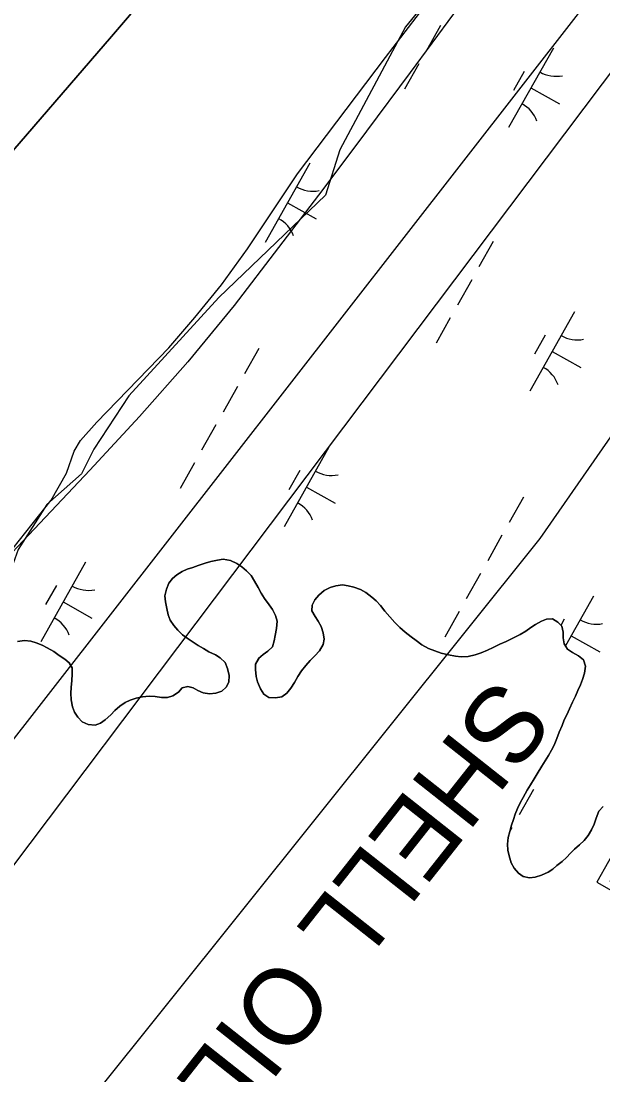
# Model space of a CAD drawing. Extents: x 3913936 to 3933962, y 195330 to 217741.
# Drawn here: x 3923117 to 3923436, y 199912 to 200489 of the extents above; entities that cross this region are included whole.
import ezdxf

# ---------------------------------------------------------------- set-up
doc = ezdxf.new("R2010")
doc.units = 0
for name, color, linetype in [('V-CHAN-DOCK', 7, 'Continuous'), ('V-RIVR-EDGE', 7, 'Continuous'), ('V-RRAP-FSHR', 7, 'Continuous'), ('V-TOPO-DPTH', 7, 'Continuous'), ('V-TOPO-MINR', 7, 'Continuous'), ('V-TOPO-SHOR', 7, 'Continuous'), ('V-UTIL-IDEN', 7, 'Continuous'), ('V-UTIL-LINE', 7, 'Continuous'), ('V-WETL-SWMP', 7, 'Continuous')]:
    doc.layers.add(name, color=color, linetype=linetype)

msp = doc.modelspace()

# ---------------------------------------------------------------- linework, layer by layer
at = {"layer": 'V-CHAN-DOCK'}
msp.add_lwpolyline([(3923458.56, 200062.78), (3923432.96, 200017.59), (3923444.96, 200010.79), (3923446.47, 200013.46), (3923481.36, 199993.7), (3923483.16, 199996.89), (3923495.74, 199989.76), (3923498.67, 199994.95), (3923485.34, 200002.5), (3923482.61, 199997.68), (3923446.17, 200018.32), (3923444.63, 200015.6), (3923440.35, 200018.02), (3923463.97, 200059.72)], close=True, dxfattribs=at)
at = {"layer": 'V-RIVR-EDGE'}
msp.add_lwpolyline([(3923413.52, 200590.76), (3923328.14, 200486.28), (3923292.19, 200418.88), (3923284.33, 200394.16), (3923225.91, 200337.99), (3923176.48, 200284.07), (3923157.38, 200254.86), (3923150.64, 200241.38), (3923131.55, 200224.53), (3923115.82, 200199.81), (3923105.71, 200171.73), (3923101.21, 200151.51), (3923091.1, 200144.77), (3923078.75, 200144.77), (3923064.14, 200130.16), (3923051.78, 200097.58), (3923032.69, 200079.61), (3923010.22, 200067.25), (3922975.39, 200050.4), (3922915.85, 200002.09), (3922760.82, 199830.21)], dxfattribs=at)
at = {"layer": 'V-RRAP-FSHR'}
msp.add_lwpolyline([(3923354.41, 200493.48), (3923330.62, 200461.33), (3923306.83, 200429.17), (3923282.85, 200397.16), (3923258.52, 200365.42), (3923234.18, 200333.67), (3923208.83, 200302.73), (3923182.44, 200272.68), (3923155.23, 200243.36), (3923127.68, 200214.36), (3923100.29, 200185.46), (3923072.29, 200156.64), (3923044.53, 200127.85), (3923016.74, 200099.77), (3922988.95, 200070.3)], dxfattribs=at)
at = {"layer": 'V-TOPO-DPTH'}
msp.add_lwpolyline([(3923572.36, 200998.52), (3923503.91, 200907.2), (3923435.27, 200816.03), (3923326.2, 200671.67), (3923311.77, 200652.93), (3923297.12, 200634.37), (3923282.13, 200616.08), (3923266.93, 200597.97), (3923166.97, 200481.11), (3923101.22, 200405.05), (3923034.94, 200329.46), (3922967.87, 200254.57), (3922900.28, 200180.15), (3922705.27, 199967.65), (3922675.93, 199934.9), (3922647.14, 199901.69), (3922619.17, 199867.8), (3922591.73, 199833.44), (3922552.62, 199783.23), (3922506.1, 199723.37), (3922459.66, 199663.45), (3922413.34, 199603.44), (3922367.1, 199543.37), (3922084.4, 199175.27)], dxfattribs=at)
at = {"layer": 'V-TOPO-MINR'}
msp.add_lwpolyline([(3922084.4, 199175.27), (3922367.1, 199543.37), (3922413.34, 199603.44), (3922459.66, 199663.45), (3922506.1, 199723.37), (3922552.62, 199783.23), (3922591.73, 199833.44), (3922619.17, 199867.8), (3922647.14, 199901.69), (3922675.93, 199934.9), (3922705.27, 199967.65), (3922900.28, 200180.15), (3922967.87, 200254.57), (3923034.94, 200329.46), (3923101.22, 200405.05), (3923166.97, 200481.11), (3923266.93, 200597.97), (3923282.13, 200616.08), (3923297.12, 200634.37), (3923311.77, 200652.93), (3923326.2, 200671.67), (3923435.27, 200816.03), (3923503.91, 200907.2), (3923572.36, 200998.52)], dxfattribs=at)
at = {"layer": 'V-TOPO-SHOR'}
for points in [[(3923168.92, 200111.58), (3923171.51, 200113.92), (3923174.44, 200116.09), (3923177.21, 200117.31), (3923180.58, 200118.45), (3923183.95, 200119.06), (3923187.67, 200119.51), (3923190.87, 200119.26), (3923194.51, 200118.75), (3923197.62, 200118.84), (3923200.56, 200119.71), (3923203.76, 200121.71), (3923205.83, 200123.97), (3923208.77, 200124.75), (3923211.71, 200124.07), (3923214.4, 200122.61), (3923217.34, 200121.4), (3923220.72, 200120.72), (3923224.26, 200121.08), (3923227.46, 200122.21), (3923229.79, 200124.47), (3923231.34, 200127.24), (3923231.5, 200130.87), (3923230.63, 200134.68), (3923229.32, 200137.96), (3923226.63, 200140.46), (3923223.95, 200142.1), (3923220.31, 200143.82), (3923217.36, 200145.54), (3923214.59, 200147.18), (3923211.73, 200149.16), (3923208.43, 200151.32), (3923206.01, 200153.13), (3923203.4, 200155.71), (3923201.15, 200158.3), (3923199.24, 200161.07), (3923198.1, 200164.09), (3923197.31, 200167.46), (3923196.61, 200171.1), (3923196.26, 200174.56), (3923197.11, 200178.19), (3923198.49, 200181.4), (3923200.47, 200183.91), (3923202.89, 200185.91), (3923205.74, 200187.82), (3923208.5, 200189.04), (3923211.53, 200190.09), (3923214.55, 200191.13), (3923218.36, 200192.44), (3923221.38, 200193.31), (3923225.19, 200194.1), (3923228.3, 200194.54), (3923232.28, 200193.86), (3923235.75, 200192.23), (3923238.52, 200190.42), (3923241.04, 200188.09), (3923243.55, 200185.59), (3923245.38, 200182.57), (3923247.38, 200179.11), (3923249.03, 200176), (3923250.86, 200173.07), (3923253.37, 200169.61), (3923255.28, 200167.02), (3923256.85, 200163.74), (3923257.81, 200160.54), (3923257.48, 200156.64), (3923256.79, 200152.75), (3923256.2, 200149.72), (3923255.17, 200146.6), (3923252.67, 200144.09), (3923250.16, 200142.35), (3923247.49, 200140.09), (3923246.02, 200137.23), (3923245.94, 200134.03), (3923246.39, 200130.31), (3923247.09, 200127.29), (3923248.74, 200123.48), (3923250.57, 200120.63), (3923253.26, 200118.82), (3923256.98, 200118.57), (3923260.35, 200119.19), (3923263.03, 200121.1), (3923265.27, 200123.79), (3923267.25, 200126.99), (3923269.06, 200130.2), (3923271.12, 200133.41), (3923273.45, 200136.36), (3923275.87, 200139.05), (3923278.37, 200141.56), (3923281.04, 200144.34), (3923283.11, 200147.72), (3923283.54, 200150.75), (3923283, 200154.12), (3923281.87, 200157.66), (3923280.31, 200160.52), (3923278.57, 200163.19), (3923276.74, 200166.21), (3923276.91, 200169.42), (3923278.54, 200172.36), (3923280.7, 200174.88), (3923283.55, 200177.31)], [(3923283.55, 200177.31), (3923286.83, 200178.96), (3923290.03, 200180.01), (3923293.58, 200180.45), (3923296.69, 200180.03), (3923299.81, 200179.26), (3923303.44, 200177.97), (3923306.48, 200176.25), (3923309.69, 200173.83), (3923312.03, 200171.76), (3923314.37, 200169.18), (3923316.89, 200166.07), (3923319.58, 200163.05), (3923322.27, 200159.94), (3923325.05, 200157.18), (3923328, 200154.59), (3923331.29, 200152), (3923333.98, 200149.94), (3923337.1, 200147.61), (3923340.83, 200145.63), (3923344.29, 200144.25), (3923347.67, 200143.14), (3923351.65, 200142.11), (3923355.54, 200141.43), (3923358.66, 200141.01), (3923362.55, 200141.28), (3923366.36, 200142.07), (3923369.56, 200143.2), (3923373.1, 200144.68), (3923376.12, 200146.16), (3923379.93, 200147.9), (3923383.3, 200149.47), (3923387.27, 200151.47), (3923390.9, 200153.21), (3923394.01, 200155.12), (3923396.77, 200157.03), (3923399.45, 200158.77), (3923402.65, 200160.51), (3923405.5, 200161.64), (3923408.7, 200161.91), (3923411.64, 200160.1), (3923413.73, 200157.77), (3923414.52, 200154.49), (3923414.61, 200151.46), (3923415.05, 200148.17), (3923416.88, 200145.32), (3923419.74, 200143.34), (3923422.95, 200141.62), (3923425.72, 200139.46), (3923426.85, 200136), (3923426.26, 200132.11), (3923425.23, 200128.56), (3923424.11, 200125.7), (3923422.57, 200122.58), (3923421.28, 200119.46), (3923419.73, 200116.17), (3923418.09, 200112.62), (3923416.54, 200109.33), (3923415.17, 200106.47), (3923413.97, 200103.44), (3923412.42, 200099.8), (3923411.13, 200096.33), (3923409.58, 200092.7), (3923408.12, 200089.92), (3923406.57, 200086.98), (3923404.76, 200084.12), (3923402.78, 200081.08), (3923400.37, 200076.93), (3923398.73, 200074.24), (3923396.67, 200070.95), (3923394.86, 200067.91), (3923392.71, 200063.92), (3923391.07, 200060.98), (3923389.61, 200057.95), (3923388.32, 200054.83), (3923387.29, 200051.97), (3923386.26, 200048.77), (3923385.23, 200045.3), (3923384.46, 200042.01), (3923384.04, 200038.29), (3923384.22, 200035.09), (3923384.92, 200031.89), (3923386.14, 200028.17), (3923387.62, 200025.15), (3923390.05, 200022.56), (3923392.57, 200020.67), (3923396.03, 200019.98), (3923399.23, 200020.34), (3923402.69, 200021.39), (3923406.32, 200023.04), (3923408.82, 200024.69), (3923411.15, 200026.6), (3923414, 200028.94), (3923416.42, 200031.11), (3923418.49, 200033.37), (3923420.82, 200035.71), (3923423.58, 200037.97), (3923426, 200040.31), (3923428.24, 200043.09), (3923430.13, 200046.29), (3923431.59, 200049.41)], [(3923115.52, 200149.5), (3923119.41, 200149.94), (3923122.78, 200149.61), (3923125.73, 200148.75), (3923129.02, 200147.46), (3923131.79, 200145.91), (3923135.34, 200143.93), (3923138.29, 200141.86), (3923141.41, 200139.71), (3923143.75, 200137.73), (3923145.41, 200134.96), (3923145.5, 200131.59), (3923145.25, 200128.13), (3923144.92, 200124.23), (3923144.75, 200121.2), (3923144.85, 200117.48), (3923145.64, 200113.68), (3923146.68, 200110.65), (3923148.6, 200107.89), (3923150.94, 200105.47), (3923154.23, 200103.92), (3923158.04, 200103.68), (3923160.98, 200104.72), (3923163.57, 200106.55), (3923166.59, 200109.33), (3923168.92, 200111.58)], [(3923431.59, 200049.41), (3923432.62, 200052.62), (3923434.17, 200056.51), (3923436.5, 200058.94)]]:
    msp.add_lwpolyline(points, dxfattribs=at)
at = {"layer": 'V-UTIL-LINE'}
for points in [[(3922259.35, 198607.65), (3922481.8, 198996.51), (3922891.23, 199568.37), (3923401.91, 200205.88), (3924391.34, 201632.88), (3925141.51, 202100.49), (3925635.89, 202689.84), (3926060.57, 203224.55), (3926266.36, 203722.12), (3926398.76, 204373.14), (3926759.45, 205211.96), (3927229.53, 206070.79), (3927602.51, 206766.2), (3928031.78, 207586.17)], [(3924418.51, 201773.34), (3922973.72, 199916.81)], [(3922166.91, 198676.44), (3922606.64, 199354.27), (3923719.03, 200830.83), (3923718.13, 200956.52)]]:
    msp.add_lwpolyline(points, dxfattribs=at)
at = {"layer": 'V-WETL-SWMP'}
for p, q in [((3923317.19, 200469.49), (3923423.3, 200608.03)), ((3923347.24, 200487), (3923339.4, 200473.06)), ((3923409.16, 200474.65), (3923384.66, 200431.07)), ((3923268.96, 200405.84), (3923317.19, 200469.49)), ((3923335.48, 200466.08), (3923327.63, 200452.13)), ((3923393.13, 200461.87), (3923387.25, 200451.41)), ((3923396.91, 200452.86), (3923412.6, 200444.04)), ((3923275.8, 200411.69), (3923251.29, 200368.11)), ((3923253.92, 200383.34), (3923268.96, 200405.84)), ((3923263.54, 200389.9), (3923279.24, 200381.08)), ((3923241.58, 200364.72), (3923253.92, 200383.34)), ((3923376.22, 200368.67), (3923368.38, 200354.72)), ((3923227.31, 200344.93), (3923241.58, 200364.72)), ((3923212.65, 200327.07), (3923227.31, 200344.93)), ((3923364.46, 200347.75), (3923356.62, 200333.8)), ((3923198.36, 200310.38), (3923212.65, 200327.07)), ((3923352.7, 200326.82), (3923344.86, 200312.88)), ((3923420.79, 200330.18), (3923396.29, 200286.6)), ((3923404.76, 200317.4), (3923398.88, 200306.94)), ((3923158.98, 200269.61), (3923198.36, 200310.38)), ((3923247.78, 200310.09), (3923239.94, 200296.14)), ((3923408.54, 200308.39), (3923424.23, 200299.57)), ((3923236.02, 200289.17), (3923228.18, 200275.22)), ((3923150.1, 200259.52), (3923158.98, 200269.61)), ((3923224.26, 200268.24), (3923216.42, 200254.3)), ((3923146.63, 200253.7), (3923150.1, 200259.52)), ((3923142.41, 200241.68), (3923146.63, 200253.7)), ((3923286.19, 200255.89), (3923261.69, 200212.31)), ((3923212.5, 200247.32), (3923204.66, 200233.38)), ((3923133.93, 200226.95), (3923142.41, 200241.68)), ((3923270.15, 200243.11), (3923264.27, 200232.65)), ((3923273.94, 200234.1), (3923289.63, 200225.28)), ((3923392.78, 200228.58), (3923384.94, 200214.63)), ((3923113.09, 200200.56), (3923133.93, 200226.95)), ((3923381.02, 200207.66), (3923373.18, 200193.71)), ((3923221.38, 200193.31), (3923218.36, 200192.44)), ((3923225.19, 200194.1), (3923221.38, 200193.31)), ((3923228.3, 200194.55), (3923225.19, 200194.1)), ((3923232.28, 200193.86), (3923228.3, 200194.55)), ((3923235.75, 200192.23), (3923232.28, 200193.86)), ((3923152.82, 200192.93), (3923128.32, 200149.35)), ((3923205.74, 200187.82), (3923202.89, 200185.91)), ((3923208.5, 200189.04), (3923205.74, 200187.82)), ((3923211.53, 200190.09), (3923208.5, 200189.04)), ((3923214.55, 200191.13), (3923211.53, 200190.09)), ((3923218.36, 200192.44), (3923214.55, 200191.13)), ((3923238.52, 200190.42), (3923235.75, 200192.23)), ((3923241.04, 200188.09), (3923238.52, 200190.42)), ((3923243.55, 200185.59), (3923241.04, 200188.09)), ((3923200.47, 200183.91), (3923198.49, 200181.4)), ((3923202.89, 200185.91), (3923200.47, 200183.91)), ((3923245.38, 200182.57), (3923243.55, 200185.59)), ((3923247.38, 200179.11), (3923245.38, 200182.57)), ((3923369.26, 200186.73), (3923361.42, 200172.79)), ((3923136.79, 200180.15), (3923130.91, 200169.69)), ((3923197.11, 200178.19), (3923196.26, 200174.56)), ((3923198.49, 200181.4), (3923197.11, 200178.19)), ((3923249.03, 200176), (3923247.38, 200179.11)), ((3923250.85, 200173.06), (3923249.03, 200176)), ((3923283.55, 200177.31), (3923280.7, 200174.88)), ((3923286.83, 200178.96), (3923283.55, 200177.31)), ((3923290.03, 200180.01), (3923286.83, 200178.96)), ((3923293.58, 200180.45), (3923290.03, 200180.01)), ((3923296.69, 200180.03), (3923293.58, 200180.45)), ((3923299.81, 200179.26), (3923296.69, 200180.03)), ((3923303.45, 200177.97), (3923299.81, 200179.26)), ((3923306.48, 200176.25), (3923303.45, 200177.97)), ((3923309.69, 200173.83), (3923306.48, 200176.25)), ((3923140.57, 200171.14), (3923156.26, 200162.32)), ((3923196.26, 200174.56), (3923196.61, 200171.1)), ((3923196.61, 200171.1), (3923197.31, 200167.46)), ((3923253.37, 200169.61), (3923250.85, 200173.06)), ((3923278.54, 200172.36), (3923276.91, 200169.42)), ((3923280.7, 200174.88), (3923278.54, 200172.36)), ((3923312.03, 200171.76), (3923309.69, 200173.83)), ((3923314.37, 200169.18), (3923312.03, 200171.76)), ((3923431.19, 200174.38), (3923415.8, 200147.01)), ((3923197.31, 200167.46), (3923198.1, 200164.09)), ((3923255.28, 200167.02), (3923253.37, 200169.61)), ((3923256.85, 200163.74), (3923255.28, 200167.02)), ((3923276.91, 200169.42), (3923276.74, 200166.21)), ((3923276.74, 200166.21), (3923278.57, 200163.19)), ((3923316.89, 200166.07), (3923314.37, 200169.18)), ((3923319.58, 200163.05), (3923316.89, 200166.07)), ((3923357.5, 200165.81), (3923349.66, 200151.87)), ((3923198.1, 200164.09), (3923199.24, 200161.07)), ((3923199.24, 200161.07), (3923201.15, 200158.3)), ((3923257.81, 200160.54), (3923256.85, 200163.74)), ((3923257.48, 200156.64), (3923257.81, 200160.54)), ((3923278.57, 200163.19), (3923280.31, 200160.52)), ((3923280.31, 200160.52), (3923281.87, 200157.66)), ((3923322.27, 200159.94), (3923319.58, 200163.05)), ((3923325.05, 200157.18), (3923322.27, 200159.94)), ((3923399.45, 200158.77), (3923396.77, 200157.03)), ((3923402.65, 200160.51), (3923399.45, 200158.77)), ((3923405.5, 200161.64), (3923402.65, 200160.51)), ((3923408.7, 200161.91), (3923405.5, 200161.64)), ((3923411.65, 200160.1), (3923408.7, 200161.91)), ((3923413.73, 200157.77), (3923411.65, 200160.1)), ((3923415.15, 200161.6), (3923413.28, 200158.27)), ((3923201.15, 200158.3), (3923203.4, 200155.71)), ((3923203.4, 200155.71), (3923206.01, 200153.13)), ((3923206.01, 200153.13), (3923208.43, 200151.32)), ((3923256.2, 200149.72), (3923256.79, 200152.75)), ((3923256.79, 200152.75), (3923257.48, 200156.64)), ((3923281.87, 200157.66), (3923283.01, 200154.12)), ((3923283.01, 200154.12), (3923283.54, 200150.75)), ((3923328, 200154.59), (3923325.05, 200157.18)), ((3923331.29, 200152), (3923328, 200154.59)), ((3923390.9, 200153.21), (3923387.27, 200151.47)), ((3923394.01, 200155.12), (3923390.9, 200153.21)), ((3923396.77, 200157.03), (3923394.01, 200155.12)), ((3923414.52, 200154.49), (3923413.73, 200157.77)), ((3923414.61, 200151.46), (3923414.52, 200154.49)), ((3923119.41, 200149.94), (3923115.52, 200149.5)), ((3923122.78, 200149.61), (3923119.41, 200149.94)), ((3923125.73, 200148.75), (3923122.78, 200149.61)), ((3923129.02, 200147.46), (3923125.73, 200148.75)), ((3923131.79, 200145.91), (3923129.02, 200147.46)), ((3923208.43, 200151.32), (3923211.73, 200149.16)), ((3923211.73, 200149.16), (3923214.59, 200147.18)), ((3923214.59, 200147.18), (3923217.36, 200145.54)), ((3923255.17, 200146.6), (3923256.2, 200149.72)), ((3923283.11, 200147.72), (3923281.04, 200144.34)), ((3923283.54, 200150.75), (3923283.11, 200147.72)), ((3923333.98, 200149.94), (3923331.29, 200152)), ((3923337.1, 200147.61), (3923333.98, 200149.94)), ((3923340.83, 200145.63), (3923337.1, 200147.61)), ((3923379.93, 200147.9), (3923376.12, 200146.16)), ((3923383.3, 200149.47), (3923379.93, 200147.9)), ((3923387.27, 200151.47), (3923383.3, 200149.47)), ((3923415.05, 200148.17), (3923414.61, 200151.46)), ((3923416.88, 200145.32), (3923415.05, 200148.17)), ((3923418.94, 200152.59), (3923434.63, 200143.77)), ((3923135.35, 200143.93), (3923131.79, 200145.91)), ((3923138.29, 200141.86), (3923135.35, 200143.93)), ((3923141.41, 200139.71), (3923138.29, 200141.86)), ((3923217.36, 200145.54), (3923220.31, 200143.82)), ((3923220.31, 200143.82), (3923223.95, 200142.1)), ((3923223.95, 200142.1), (3923226.63, 200140.46)), ((3923247.49, 200140.09), (3923250.16, 200142.35)), ((3923250.16, 200142.35), (3923252.67, 200144.08)), ((3923252.67, 200144.08), (3923255.17, 200146.6)), ((3923278.37, 200141.56), (3923275.87, 200139.05)), ((3923281.04, 200144.34), (3923278.37, 200141.56)), ((3923344.29, 200144.25), (3923340.83, 200145.63)), ((3923347.67, 200143.14), (3923344.29, 200144.25)), ((3923351.65, 200142.11), (3923347.67, 200143.14)), ((3923355.55, 200141.43), (3923351.65, 200142.11)), ((3923358.66, 200141.01), (3923355.55, 200141.43)), ((3923362.55, 200141.28), (3923358.66, 200141.01)), ((3923366.36, 200142.07), (3923362.55, 200141.28)), ((3923369.56, 200143.2), (3923366.36, 200142.07)), ((3923373.1, 200144.68), (3923369.56, 200143.2)), ((3923376.12, 200146.16), (3923373.1, 200144.68)), ((3923419.74, 200143.34), (3923416.88, 200145.32)), ((3923422.94, 200141.62), (3923419.74, 200143.34)), ((3923425.72, 200139.46), (3923422.94, 200141.62)), ((3923143.75, 200137.73), (3923141.41, 200139.71)), ((3923145.41, 200134.96), (3923143.75, 200137.73)), ((3923226.63, 200140.46), (3923229.32, 200137.96)), ((3923229.32, 200137.96), (3923230.63, 200134.68)), ((3923245.95, 200134.03), (3923246.02, 200137.23)), ((3923247.94, 200140.47), (3923246.02, 200137.06)), ((3923246.02, 200137.23), (3923247.49, 200140.09)), ((3923273.45, 200136.36), (3923271.12, 200133.41)), ((3923275.87, 200139.05), (3923273.45, 200136.36)), ((3923426.85, 200136.01), (3923425.72, 200139.46)), ((3923426.26, 200132.11), (3923426.85, 200136.01)), ((3923145.25, 200128.13), (3923145.5, 200131.59)), ((3923145.5, 200131.59), (3923145.41, 200134.96)), ((3923230.63, 200134.68), (3923231.5, 200130.87)), ((3923231.5, 200130.87), (3923231.34, 200127.24)), ((3923246.39, 200130.31), (3923245.95, 200134.03)), ((3923247.09, 200127.29), (3923246.39, 200130.31)), ((3923269.06, 200130.2), (3923267.25, 200126.99)), ((3923271.12, 200133.41), (3923269.06, 200130.2)), ((3923425.23, 200128.56), (3923426.26, 200132.11)), ((3923144.75, 200121.2), (3923144.92, 200124.23)), ((3923144.92, 200124.23), (3923145.25, 200128.13)), ((3923205.83, 200123.97), (3923203.76, 200121.71)), ((3923208.77, 200124.75), (3923205.83, 200123.97)), ((3923211.71, 200124.07), (3923208.77, 200124.75)), ((3923214.4, 200122.61), (3923211.71, 200124.07)), ((3923229.79, 200124.47), (3923227.46, 200122.21)), ((3923231.34, 200127.24), (3923229.79, 200124.47)), ((3923248.74, 200123.48), (3923247.09, 200127.29)), ((3923267.25, 200126.99), (3923265.27, 200123.79)), ((3923422.56, 200122.58), (3923424.11, 200125.7)), ((3923424.11, 200125.7), (3923425.23, 200128.56)), ((3923144.85, 200117.48), (3923144.75, 200121.2)), ((3923180.58, 200118.45), (3923177.21, 200117.31)), ((3923183.95, 200119.06), (3923180.58, 200118.45)), ((3923187.67, 200119.5), (3923183.95, 200119.06)), ((3923190.87, 200119.26), (3923187.67, 200119.5)), ((3923194.51, 200118.75), (3923190.87, 200119.26)), ((3923197.62, 200118.84), (3923194.51, 200118.75)), ((3923200.56, 200119.71), (3923197.62, 200118.84)), ((3923203.76, 200121.71), (3923200.56, 200119.71)), ((3923217.34, 200121.4), (3923214.4, 200122.61)), ((3923220.72, 200120.72), (3923217.34, 200121.4)), ((3923224.27, 200121.08), (3923220.72, 200120.72)), ((3923227.46, 200122.21), (3923224.27, 200121.08)), ((3923250.57, 200120.63), (3923248.74, 200123.48)), ((3923253.25, 200118.82), (3923250.57, 200120.63)), ((3923256.98, 200118.57), (3923253.25, 200118.82)), ((3923260.35, 200119.19), (3923256.98, 200118.57)), ((3923263.03, 200121.1), (3923260.35, 200119.19)), ((3923265.27, 200123.79), (3923263.03, 200121.1)), ((3923419.73, 200116.17), (3923421.28, 200119.46)), ((3923421.28, 200119.46), (3923422.56, 200122.58)), ((3923145.64, 200113.68), (3923144.85, 200117.48)), ((3923146.69, 200110.65), (3923145.64, 200113.68)), ((3923171.51, 200113.92), (3923168.92, 200111.58)), ((3923174.44, 200116.09), (3923171.51, 200113.92)), ((3923177.21, 200117.31), (3923174.44, 200116.09)), ((3923416.54, 200109.33), (3923418.09, 200112.62)), ((3923418.09, 200112.62), (3923419.73, 200116.17)), ((3923148.6, 200107.89), (3923146.69, 200110.65)), ((3923150.94, 200105.47), (3923148.6, 200107.89)), ((3923163.57, 200106.55), (3923160.98, 200104.72)), ((3923166.59, 200109.32), (3923163.57, 200106.55)), ((3923168.92, 200111.58), (3923166.59, 200109.32)), ((3923415.17, 200106.47), (3923416.54, 200109.33)), ((3923154.23, 200103.92), (3923150.94, 200105.47)), ((3923158.04, 200103.68), (3923154.23, 200103.92)), ((3923160.98, 200104.72), (3923158.04, 200103.68)), ((3923412.42, 200099.8), (3923413.97, 200103.44)), ((3923413.97, 200103.44), (3923415.17, 200106.47)), ((3923409.58, 200092.7), (3923411.13, 200096.33)), ((3923411.13, 200096.33), (3923412.42, 200099.8)), ((3923406.57, 200086.98), (3923408.12, 200089.92)), ((3923408.12, 200089.92), (3923409.58, 200092.7)), ((3923402.78, 200081.08), (3923404.76, 200084.12)), ((3923404.76, 200084.12), (3923406.57, 200086.98)), ((3923400.37, 200076.93), (3923402.78, 200081.08)), ((3923396.67, 200070.95), (3923398.73, 200074.24)), ((3923398.73, 200074.24), (3923400.37, 200076.93)), ((3923398.24, 200068.4), (3923390.4, 200054.45)), ((3923392.71, 200063.92), (3923394.86, 200067.91)), ((3923394.86, 200067.91), (3923396.67, 200070.95)), ((3923389.61, 200057.95), (3923391.07, 200060.98)), ((3923391.07, 200060.98), (3923392.71, 200063.92)), ((3923387.29, 200051.97), (3923388.32, 200054.83)), ((3923388.32, 200054.83), (3923389.61, 200057.95)), ((3923434.17, 200056.51), (3923432.62, 200052.62)), ((3923436.5, 200058.94), (3923434.17, 200056.51)), ((3923385.23, 200045.3), (3923386.26, 200048.77)), ((3923386.26, 200048.77), (3923387.29, 200051.97)), ((3923431.59, 200049.41), (3923430.13, 200046.29)), ((3923432.62, 200052.62), (3923431.59, 200049.41)), ((3923384.46, 200042.01), (3923385.23, 200045.3)), ((3923386.48, 200047.48), (3923385.21, 200045.22)), ((3923428.24, 200043.09), (3923426, 200040.31)), ((3923430.13, 200046.29), (3923428.24, 200043.09)), ((3923384.04, 200038.29), (3923384.46, 200042.01)), ((3923384.22, 200035.09), (3923384.04, 200038.29)), ((3923423.58, 200037.97), (3923420.82, 200035.71)), ((3923426, 200040.31), (3923423.58, 200037.97)), ((3923384.92, 200031.89), (3923384.22, 200035.09)), ((3923386.14, 200028.17), (3923384.92, 200031.89)), ((3923418.49, 200033.37), (3923416.42, 200031.11)), ((3923420.82, 200035.71), (3923418.49, 200033.37)), ((3923387.62, 200025.15), (3923386.14, 200028.17)), ((3923411.15, 200026.6), (3923408.82, 200024.69)), ((3923414, 200028.94), (3923411.15, 200026.6)), ((3923416.42, 200031.11), (3923414, 200028.94)), ((3923390.05, 200022.56), (3923387.62, 200025.15)), ((3923392.57, 200020.67), (3923390.05, 200022.56)), ((3923396.03, 200019.98), (3923392.57, 200020.67)), ((3923399.23, 200020.34), (3923396.03, 200019.98)), ((3923402.69, 200021.39), (3923399.23, 200020.34)), ((3923406.32, 200023.04), (3923402.69, 200021.39)), ((3923408.82, 200024.69), (3923406.32, 200023.04))]:
    msp.add_line(p, q, dxfattribs=at)
for centre, start, end in [((3923410.65, 200476.82), 239.88608, 281.42974), ((3923383.58, 200428.66), 19.88608, 61.42973), ((3923277.29, 200413.86), 239.88608, 281.42974), ((3923250.22, 200365.7), 19.88608, 61.42973), ((3923422.28, 200332.35), 239.88608, 281.42974), ((3923395.21, 200284.19), 19.88608, 61.42973), ((3923287.68, 200258.06), 239.88608, 281.42974), ((3923260.61, 200209.9), 19.88608, 61.42973), ((3923154.31, 200195.1), 239.88608, 281.42974), ((3923127.24, 200146.95), 19.88608, 61.42973), ((3923432.68, 200176.55), 239.88608, 281.42974)]:
    msp.add_arc(centre, 17.62, start, end, dxfattribs=at)

# ---------------------------------------------------------------- texts
at = {"layer": 'V-UTIL-IDEN'}
msp.add_text('SHELL OIL CO.', height=41.9999, rotation=231.6751, dxfattribs=at).set_placement((3923377.78, 200131.47))

doc.saveas('drawing.dxf')
